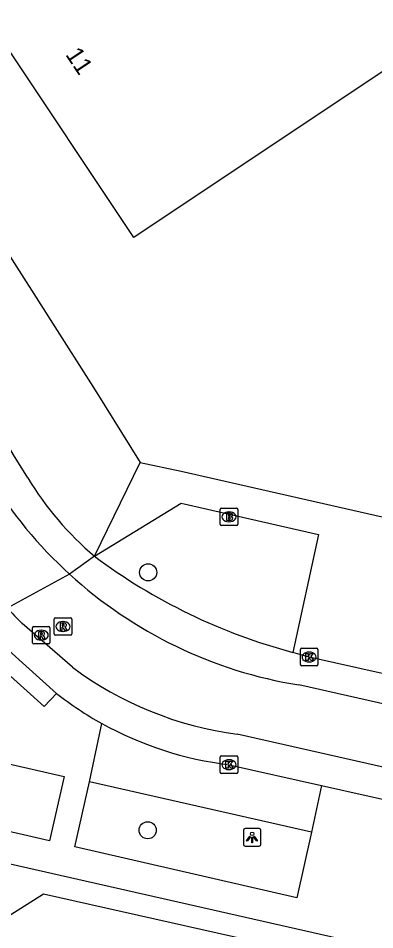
# Model space of a CAD drawing. Extents: x 161771 to 163125, y 382479 to 383177.
# Drawn here: x 162343.5 to 162363.8, y 382858.3 to 382910.3 of the extents above; entities that cross this region are included whole.
import ezdxf

# ---------------------------------------------------------------- set-up
doc = ezdxf.new("R2010")
doc.units = 0
for name, color, linetype in [('IMGEO_Boom', 7, 'Continuous'), ('IMGEO_Brandkraan', 7, 'Continuous'), ('IMGEO_Kolk', 7, 'Continuous'), ('IMGEO_Lichtpunt', 7, 'Continuous'), ('IMGEO_Pand', 7, 'Continuous'), ('IMGEO_Pand_nummerreeks', 7, 'Continuous'), ('IMGEO_Parkeervlak_open', 7, 'Continuous'), ('IMGEO_Rijbaan_lokaal_gesloten', 7, 'Continuous'), ('IMGEO_Rioolput', 7, 'Continuous'), ('IMGEO_Voetpad_open', 7, 'Continuous')]:
    doc.layers.add(name, color=color, linetype=linetype)

msp = doc.modelspace()

# ---------------------------------------------------------------- linework, layer by layer
at = {"layer": 'IMGEO_Boom'}
for centre in [(162350.875, 382878.724), (162350.847, 382864.014)]:
    msp.add_circle(centre, 0.489, dxfattribs=at)
at = {"layer": 'IMGEO_Brandkraan'}
for p, q in [((162355.064, 382882.394), (162355.916, 382882.394)), ((162354.989, 382881.468), (162354.989, 382882.32)), ((162355.477, 382882.174), (162355.502, 382882.174)), ((162355.99, 382882.32), (162355.99, 382881.468)), ((162355.916, 382881.394), (162355.064, 382881.394)), ((162355.5, 382881.614), (162355.475, 382881.614))]:
    msp.add_line(p, q, dxfattribs=at)
for points in [[(162355.064, 382882.394), (162355.916, 382882.394)], [(162354.989, 382881.468), (162354.989, 382882.32)], [(162355.337, 382882.094), (162355.337, 382881.694), (162355.55, 382881.694)], [(162355.568, 382882.094), (162355.337, 382882.094)], [(162355.516, 382882.013), (162355.462, 382882.013), (162355.462, 382881.937)], [(162355.462, 382881.937), (162355.515, 382881.937)], [(162355.524, 382881.861), (162355.462, 382881.861), (162355.462, 382881.78)], [(162355.99, 382882.32), (162355.99, 382881.468)], [(162355.916, 382881.394), (162355.064, 382881.394)], [(162355.462, 382881.78), (162355.524, 382881.78)]]:
    msp.add_lwpolyline(points, dxfattribs=at)
for centre, radius, start, end in [((162355.066, 382882.318), 0.0765, 91.552, 178.448), ((162355.066, 382882.318), 0.0765, 91.552, 178.448), ((162355.914, 382882.318), 0.0765, 1.552, 88.448), ((162355.914, 382882.318), 0.0765, 1.552, 88.448), ((162355.517, 382881.975), 0.0379, 267.8285, 90.9355), ((162355.525, 382881.82), 0.0404, 269.8759, 90.5077), ((162355.572, 382881.949), 0.145, 59.4692, 91.5367), ((162355.597, 382881.996), 0.0922, 285.5137, 58.1501), ((162355.602, 382881.804), 0.105, 301.3115, 78.989), ((162355.066, 382881.47), 0.0765, 181.552, 268.448), ((162355.066, 382881.47), 0.0765, 181.552, 268.448), ((162355.556, 382881.945), 0.251, 268.6676, 293.5347), ((162355.914, 382881.47), 0.0765, 271.552, 358.448), ((162355.914, 382881.47), 0.0765, 271.552, 358.448)]:
    msp.add_arc(centre, radius, start, end, dxfattribs=at)
for centre, major_axis, ratio, start_param, end_param in [((162355.476, 382881.894), (-0.387, 0.002), 0.722429, 4.712389, 7.853982), ((162355.501, 382881.894), (-0.39, 0.002), 0.717154, 1.570796, 4.712389)]:
    msp.add_ellipse(centre, major_axis=major_axis, ratio=ratio, start_param=start_param, end_param=end_param, dxfattribs=at)
at = {"layer": 'IMGEO_Kolk'}
for p, q in [((162359.562, 382873.471), (162359.562, 382874.323)), ((162359.637, 382874.397), (162360.489, 382874.397)), ((162360.05, 382874.177), (162360.075, 382874.177)), ((162360.563, 382874.323), (162360.563, 382873.471)), ((162360.073, 382873.617), (162360.048, 382873.617)), ((162360.489, 382873.397), (162359.637, 382873.397)), ((162354.989, 382867.327), (162354.989, 382868.179)), ((162355.064, 382868.253), (162355.916, 382868.253)), ((162355.477, 382868.033), (162355.502, 382868.033)), ((162355.99, 382868.179), (162355.99, 382867.327)), ((162355.5, 382867.473), (162355.475, 382867.473)), ((162355.916, 382867.253), (162355.064, 382867.253))]:
    msp.add_line(p, q, dxfattribs=at)
for points in [[(162359.562, 382873.471), (162359.562, 382874.323)], [(162359.637, 382874.397), (162360.489, 382874.397)], [(162359.883, 382874.097), (162360.006, 382874.097), (162360.006, 382873.946), (162360.136, 382874.097), (162360.3, 382874.097), (162360.154, 382873.946), (162360.307, 382873.697), (162360.155, 382873.697), (162360.07, 382873.861), (162360.006, 382873.794), (162360.006, 382873.697), (162359.883, 382873.697), (162359.883, 382874.097)], [(162360.563, 382874.323), (162360.563, 382873.471)], [(162360.489, 382873.397), (162359.637, 382873.397)], [(162354.989, 382867.327), (162354.989, 382868.179)], [(162355.064, 382868.253), (162355.916, 382868.253)], [(162355.31, 382867.953), (162355.433, 382867.953), (162355.433, 382867.802), (162355.563, 382867.953), (162355.727, 382867.953), (162355.581, 382867.802), (162355.734, 382867.553), (162355.582, 382867.553), (162355.497, 382867.717), (162355.433, 382867.65), (162355.433, 382867.553), (162355.31, 382867.553), (162355.31, 382867.953)], [(162355.99, 382868.179), (162355.99, 382867.327)], [(162355.916, 382867.253), (162355.064, 382867.253)]]:
    msp.add_lwpolyline(points, dxfattribs=at)
for centre, start, end in [((162359.639, 382874.321), 91.552, 178.448), ((162359.639, 382874.321), 91.552, 178.448), ((162360.487, 382874.321), 1.552, 88.448), ((162360.487, 382874.321), 1.552, 88.448), ((162359.639, 382873.473), 181.552, 268.448), ((162359.639, 382873.473), 181.552, 268.448), ((162360.487, 382873.473), 271.552, 358.448), ((162360.487, 382873.473), 271.552, 358.448), ((162355.066, 382868.177), 91.552, 178.448), ((162355.066, 382868.177), 91.552, 178.448), ((162355.914, 382868.177), 1.552, 88.448), ((162355.914, 382868.177), 1.552, 88.448), ((162355.066, 382867.329), 181.552, 268.448), ((162355.066, 382867.329), 181.552, 268.448), ((162355.914, 382867.329), 271.552, 358.448), ((162355.914, 382867.329), 271.552, 358.448)]:
    msp.add_arc(centre, 0.0765, start, end, dxfattribs=at)
for centre, major_axis, ratio, start_param, end_param in [((162360.049, 382873.897), (-0.387, 0.002), 0.722429, 4.712389, 7.853982), ((162360.074, 382873.897), (-0.39, 0.002), 0.717154, 1.570796, 4.712389), ((162355.476, 382867.753), (-0.387, 0.002), 0.722429, 4.712389, 7.853982), ((162355.501, 382867.753), (-0.39, 0.002), 0.717154, 1.570796, 4.712389)]:
    msp.add_ellipse(centre, major_axis=major_axis, ratio=ratio, start_param=start_param, end_param=end_param, dxfattribs=at)
at = {"layer": 'IMGEO_Lichtpunt'}
for p, q in [((162356.31, 382864.01), (162356.31, 382863.203)), ((162356.31, 382864.01), (162356.31, 382863.203)), ((162357.212, 382864.105), (162356.404, 382864.105)), ((162357.212, 382864.105), (162356.404, 382864.105)), ((162357.306, 382863.203), (162357.306, 382864.01)), ((162357.306, 382863.203), (162357.306, 382864.01)), ((162356.404, 382863.109), (162357.212, 382863.109)), ((162356.404, 382863.109), (162357.212, 382863.109))]:
    msp.add_line(p, q, dxfattribs=at)
for points in [[(162356.684, 382863.674), (162356.723, 382863.646), (162356.535, 382863.384), (162356.497, 382863.411), (162356.684, 382863.674)], [(162356.786, 382863.626), (162356.833, 382863.626), (162356.833, 382863.304), (162356.786, 382863.304), (162356.786, 382863.626)], [(162356.896, 382863.646), (162356.934, 382863.673), (162357.121, 382863.411), (162357.082, 382863.383), (162356.896, 382863.646)]]:
    msp.add_lwpolyline(points, dxfattribs=at)
msp.add_circle((162356.809, 382863.808), 0.0994, dxfattribs=at)
for centre, start, end in [((162356.404, 382864.01), 90, 180), ((162356.404, 382864.01), 90, 180), ((162357.212, 382864.01), 0, 90), ((162357.212, 382864.01), 0, 90), ((162356.404, 382863.203), 180, 270), ((162356.404, 382863.203), 180, 270), ((162357.212, 382863.203), 270, 0), ((162357.212, 382863.203), 270, 360)]:
    msp.add_arc(centre, 0.0946, start, end, dxfattribs=at)
at = {"layer": 'IMGEO_Pand'}
for points in [[(162364.461, 382932.073), (162377.173, 382940.548), (162388.545, 382923.491), (162376.122, 382915.209), (162352.869, 382899.707), (162350.053, 382897.83), (162348.801, 382899.707), (162338.688, 382914.864), (162338.501, 382915.18)], [(162341.144, 382844.602), (162342.248, 382849.517), (162342.15, 382849.539), (162338.047, 382856.064), (162344.898, 382860.389), (162361.162, 382856.733), (162359.833, 382850.83), (162356.312, 382851.623), (162354.068, 382841.697), (162349.298, 382820.618), (162358.291, 382806.399), (162362.501, 382805.442), (162376.753, 382814.45)]]:
    msp.add_lwpolyline(points, dxfattribs=at)
at = {"layer": 'IMGEO_Parkeervlak_open'}
msp.add_lwpolyline([(162360.2, 382863.911), (162347.519, 382866.771)], dxfattribs=at)
at = {"layer": 'IMGEO_Rijbaan_lokaal_gesloten'}
for points in [[(162344.002, 382884.116), (162343.193, 382885.422), (162339.727, 382891.336)], [(162347.819, 382879.644), (162346.383, 382878.623)], [(162346.383, 382878.623), (162342.821, 382876.69)], [(162341.158, 382875.854), (162345.639, 382871.819)], [(162346.554, 382873.321), (162343.684, 382875.811)], [(162369.842, 382871.702), (162360.063, 382873.897), (162359.131, 382874.163)], [(162522.166, 382835.638), (162521.011, 382835.897), (162466.662, 382848.102), (162359.479, 382872.3)], [(162521.175, 382832.265), (162495.043, 382838.141), (162484.827, 382840.431), (162390.023, 382861.801), (162355.961, 382869.489)], [(162355.49, 382867.753), (162360.776, 382866.57)], [(162360.776, 382866.57), (162368.939, 382864.737)]]:
    msp.add_lwpolyline(points, dxfattribs=at)
for centre, radius, start, end in [((162363.558, 382897.462), 25.493, 211.4368, 227.6457), ((162359.448, 382893.434), 18.039, 211.1026, 229.8611), ((162367.603, 382906.063), 33.006, 233.1711, 255.1258), ((162363.548, 382897.452), 25.479, 227.6459, 260.8098), ((162359.189, 382891.897), 22.342, 222.894, 226.0535), ((162358.609, 382889.451), 20.137, 233.2278, 262.4446), ((162357.902, 382887.532), 19.932, 232.0306, 240.9482), ((162357.898, 382887.573), 19.966, 241.0152, 263.0731)]:
    msp.add_arc(centre, radius, start, end, dxfattribs=at)
at = {"layer": 'IMGEO_Rioolput'}
for p, q in [((162345.585, 382876.136), (162346.437, 382876.136)), ((162344.343, 382875.64), (162345.195, 382875.64)), ((162345.51, 382875.21), (162345.51, 382876.062)), ((162345.998, 382875.916), (162346.023, 382875.916)), ((162346.511, 382876.062), (162346.511, 382875.21)), ((162344.268, 382874.714), (162344.268, 382875.566)), ((162344.756, 382875.42), (162344.781, 382875.42)), ((162345.269, 382875.566), (162345.269, 382874.714)), ((162346.437, 382875.136), (162345.585, 382875.136)), ((162346.021, 382875.356), (162345.996, 382875.356)), ((162345.195, 382874.64), (162344.343, 382874.64)), ((162344.779, 382874.86), (162344.754, 382874.86))]:
    msp.add_line(p, q, dxfattribs=at)
for points in [[(162345.585, 382876.136), (162346.437, 382876.136)], [(162344.343, 382875.64), (162345.195, 382875.64)], [(162345.51, 382875.21), (162345.51, 382876.062)], [(162346.099, 382875.834), (162345.847, 382875.836), (162345.847, 382875.436)], [(162345.847, 382875.436), (162345.971, 382875.436), (162345.971, 382875.598), (162345.982, 382875.598)], [(162346.025, 382875.755), (162345.971, 382875.755), (162345.971, 382875.674)], [(162345.971, 382875.674), (162346.023, 382875.674)], [(162346.511, 382876.062), (162346.511, 382875.21)], [(162344.268, 382874.714), (162344.268, 382875.566)], [(162344.857, 382875.338), (162344.605, 382875.34), (162344.605, 382874.94)], [(162344.605, 382874.94), (162344.729, 382874.94), (162344.729, 382875.102), (162344.74, 382875.102)], [(162344.783, 382875.259), (162344.729, 382875.259), (162344.729, 382875.178)], [(162344.729, 382875.178), (162344.781, 382875.178)], [(162344.787, 382875.073), (162344.858, 382874.94), (162344.998, 382874.94), (162344.933, 382875.066)], [(162345.269, 382875.566), (162345.269, 382874.714)], [(162346.437, 382875.136), (162345.585, 382875.136)], [(162346.029, 382875.569), (162346.1, 382875.436), (162346.24, 382875.436), (162346.175, 382875.562)], [(162345.195, 382874.64), (162344.343, 382874.64)]]:
    msp.add_lwpolyline(points, dxfattribs=at)
for centre, radius, start, end in [((162345.587, 382876.06), 0.0765, 91.552, 178.448), ((162345.587, 382876.06), 0.0765, 91.552, 178.448), ((162346.435, 382876.06), 0.0765, 1.552, 88.448), ((162346.435, 382876.06), 0.0765, 1.552, 88.448), ((162344.345, 382875.564), 0.0765, 91.552, 178.448), ((162344.345, 382875.564), 0.0765, 91.552, 178.448), ((162345.193, 382875.564), 0.0765, 1.552, 88.448), ((162345.193, 382875.564), 0.0765, 1.552, 88.448), ((162345.981, 382875.545), 0.0533, 26.0293, 88.6989), ((162346.007, 382875.863), 0.19, 274.7715, 282.9687), ((162346.031, 382875.659), 0.0964, 77.0061, 93.1865), ((162346.045, 382875.716), 0.0378, 276.6634, 79.6772), ((162346.098, 382875.724), 0.109, 350.3612, 89.416), ((162346.096, 382875.724), 0.112, 277.5842, 350.9817), ((162346.08, 382875.509), 0.108, 29.5134, 73.7905), ((162344.739, 382875.049), 0.0533, 26.0293, 88.6989), ((162344.765, 382875.367), 0.19, 274.7715, 282.9687), ((162344.789, 382875.163), 0.0964, 77.0061, 93.1865), ((162344.803, 382875.22), 0.0378, 276.6634, 79.6772), ((162344.856, 382875.228), 0.109, 350.3612, 89.416), ((162344.854, 382875.228), 0.112, 277.5842, 350.9817), ((162344.838, 382875.013), 0.108, 29.5134, 73.7905), ((162345.587, 382875.212), 0.0765, 181.552, 268.448), ((162345.587, 382875.212), 0.0765, 181.552, 268.448), ((162346.435, 382875.212), 0.0765, 271.552, 358.448), ((162346.435, 382875.212), 0.0765, 271.552, 358.448), ((162344.345, 382874.716), 0.0765, 181.552, 268.448), ((162344.345, 382874.716), 0.0765, 181.552, 268.448), ((162345.193, 382874.716), 0.0765, 271.552, 358.448), ((162345.193, 382874.716), 0.0765, 271.552, 358.448)]:
    msp.add_arc(centre, radius, start, end, dxfattribs=at)
for centre, major_axis, ratio, start_param, end_param in [((162345.997, 382875.636), (-0.387, 0.002), 0.722429, 4.712389, 7.853982), ((162346.022, 382875.636), (-0.39, 0.002), 0.717154, 1.570796, 4.712389), ((162344.755, 382875.14), (-0.387, 0.002), 0.722429, 4.712389, 7.853982), ((162344.78, 382875.14), (-0.39, 0.002), 0.717154, 1.570796, 4.712389)]:
    msp.add_ellipse(centre, major_axis=major_axis, ratio=ratio, start_param=start_param, end_param=end_param, dxfattribs=at)
at = {"layer": 'IMGEO_Voetpad_open'}
for points in [[(162304.602, 382962.221), (162323.715, 382930.187), (162324.058, 382929.531), (162333.904, 382911.866), (162340.209, 382901.345), (162341.191, 382899.707), (162342.707, 382897.177), (162347.841, 382889.118), (162350.419, 382884.987)], [(162347.819, 382879.644), (162350.419, 382884.987)], [(162350.419, 382884.987), (162352.762, 382884.507), (162396.81, 382874.496), (162399.166, 382873.842), (162426.372, 382867.671), (162453.574, 382861.509), (162499.822, 382851.136), (162502.638, 382852.091), (162505.556, 382864.948)], [(162347.819, 382879.644), (162352.751, 382882.665), (162360.603, 382880.885), (162359.131, 382874.163)], [(162345.639, 382871.819), (162344.935, 382871.078), (162340.467, 382875.088)], [(162347.519, 382866.771), (162348.223, 382870.108)], [(162345.244, 382863.407), (162341.343, 382864.299), (162339.493, 382867.474), (162340.818, 382868.283), (162346.075, 382867.076), (162345.244, 382863.407)], [(162360.2, 382863.911), (162359.359, 382860.161), (162346.69, 382863.066), (162347.519, 382866.771)], [(162360.776, 382866.57), (162360.2, 382863.911)], [(162339.695, 382863.55), (162340.118, 382862.752), (162361.719, 382857.866)]]:
    msp.add_lwpolyline(points, dxfattribs=at)

# ---------------------------------------------------------------- texts
at = {"layer": 'IMGEO_Pand_nummerreeks'}
msp.add_text('11', height=1, rotation=303.711, dxfattribs=at).set_placement((162346.122, 382908.263))

doc.saveas('drawing.dxf')
